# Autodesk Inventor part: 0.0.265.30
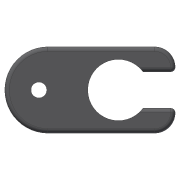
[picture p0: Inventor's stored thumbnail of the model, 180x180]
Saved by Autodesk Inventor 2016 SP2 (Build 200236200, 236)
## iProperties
Category: schwarz
Company: CAD Team Handzik
Created: 2017-10
Part Number: 0.0.265.30
Document SubType Name: Modeling
Designer: CAD Team Handzik
Density: 1 g/cm^3
Material: Allgemein
Description: Klemmlasche D80
Vendor: Item
Appearance: 128,128,128
Artikel-Nr: item_0026530_Klemmlasche_D80_schwarz
Title: Klemmlasche D80
Subject: Muster für iPart Modul
Author: CAD Team Handzik
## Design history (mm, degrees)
feature "Basis1"
node "Volumenkörper1"
node "Volumenkörper"
node "Flächenkörper"
